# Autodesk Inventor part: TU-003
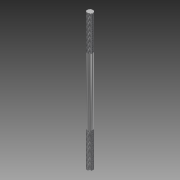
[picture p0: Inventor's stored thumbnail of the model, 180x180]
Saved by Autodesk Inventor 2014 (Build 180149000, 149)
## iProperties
Shininess: 64.0
Angle Display Precision: 2
Document Length Units: 11269
Document Angle Units: 11279
Document Time Units: 11290
Document Mass Units: 11283
Document Length Units Precision: 3
Document Angle Units Precision: 2
Compacted: True
Created: 2002-07
Part Number: TU-003
Document SubType Name: Modeling
Designer: PN
Description: M5 x 120 Threaded Rod
Mass: 18.7131 g
Surface Area: 18.8805 cm^2
Volume: 2.31598 cm^3
Density: 8.08 g/cm^3
Material: Stainless Steel
Appearance: Chrome - Polished
Density: 0.0
Volumn: 0.0
Area: 0.0
PropertySet Name: Model Information
Control State: 0
Master: False
Checked Out: False
Author: PN
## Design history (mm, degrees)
sketch "Sketch1"
  geometry: C1 r 2.5 at (0, 0); 1 further point
  constraints: 1 centre point, 1 coincident
  dimensions: "d0" = 5 diameter of C1
extrude "Extrusion1" new body sketch "Sketch1" stored distance "d1" = 118; taper "d2" = 0 deg
chamfer "Chamfer1" distance "d3" = 0.25; stored, may be unused: second distance "d4" = 0.25, angle "d7" = 45 deg
thread "Thread1" dims "d5" = 30, "d6" = 0
thread "Thread2" dims "d8" = 30, "d9" = 0
body "Solid1"
